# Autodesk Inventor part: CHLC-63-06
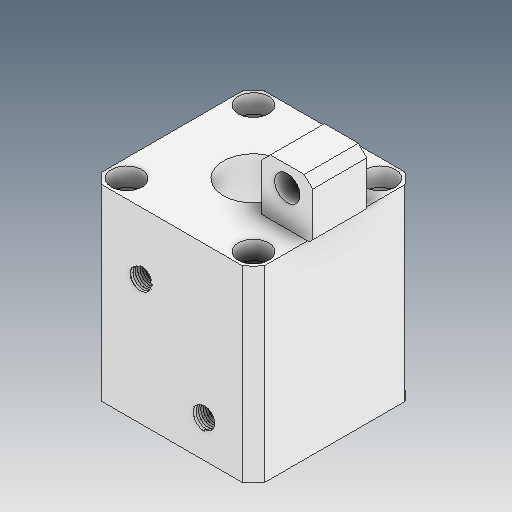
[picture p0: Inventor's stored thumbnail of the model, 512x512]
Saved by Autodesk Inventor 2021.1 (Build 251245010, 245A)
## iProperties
Created: 2021-05
Part Number: CHLC-63-06
Material: Ogólny
Document SubType Name: Modeling
Designer: user
Density: 1 g/cm^3
Appearance: Domyślna
Author: user
Revision Number: ÈÎºÎ
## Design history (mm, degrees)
feature "ÊäÈë1"
node "Bryła1"
